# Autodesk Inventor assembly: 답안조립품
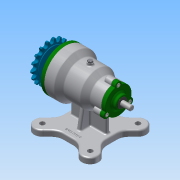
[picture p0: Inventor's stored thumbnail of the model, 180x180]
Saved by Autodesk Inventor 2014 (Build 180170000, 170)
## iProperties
Created: 2017-03
Part Number: 답안조립품
Document SubType Name: Assembly
Designer: NET
Author: NET
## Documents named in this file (14)
- C:\Users\NET\Desktop\470307V1021\답안조립품.iam
- C:\Users\NET\Desktop\470307V1021\답안본체.ipt
- C:\Users\NET\Desktop\470307V1021\축.ipt
- C:\Users\NET\Desktop\470307V1021\베어링-6203.ipt
- C:\Users\NET\Desktop\470307V1021\베어링-6200.ipt
- C:\Users\NET\Desktop\470307V1021\오일 실 17 30 8.ipt
- C:\Users\NET\Desktop\470307V1021\앞커버.ipt
- C:\Users\NET\Desktop\470307V1021\뒤커버.ipt
- C:\Users\NET\Desktop\470307V1021\오일 실 10 20 7.ipt
- C:\Users\NET\Desktop\470307V1021\키5x5.ipt
- C:\Users\NET\Desktop\470307V1021\스프로킷.ipt
- C:\Users\NET\Desktop\470307V1021\볼트 M5 x 10.ipt
- 볼트 M5 x 10.ipt
- C:\Users\NET\Desktop\470307V1021\볼트 M4 x 12.ipt
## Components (9 placed, 1 different names)
1. ISO 4762 M4 x 12:1
2. ISO 4762 M4 x 12:2
3. ISO 4762 M4 x 12:3
4. ISO 4762 M4 x 12:4
5. ISO 4762 M4 x 12:5
6. ISO 4762 M4 x 12:6
7. ISO 4762 M4 x 12:7
8. ISO 4762 M4 x 12:8
9. ISO 4762 M4 x 12:9
